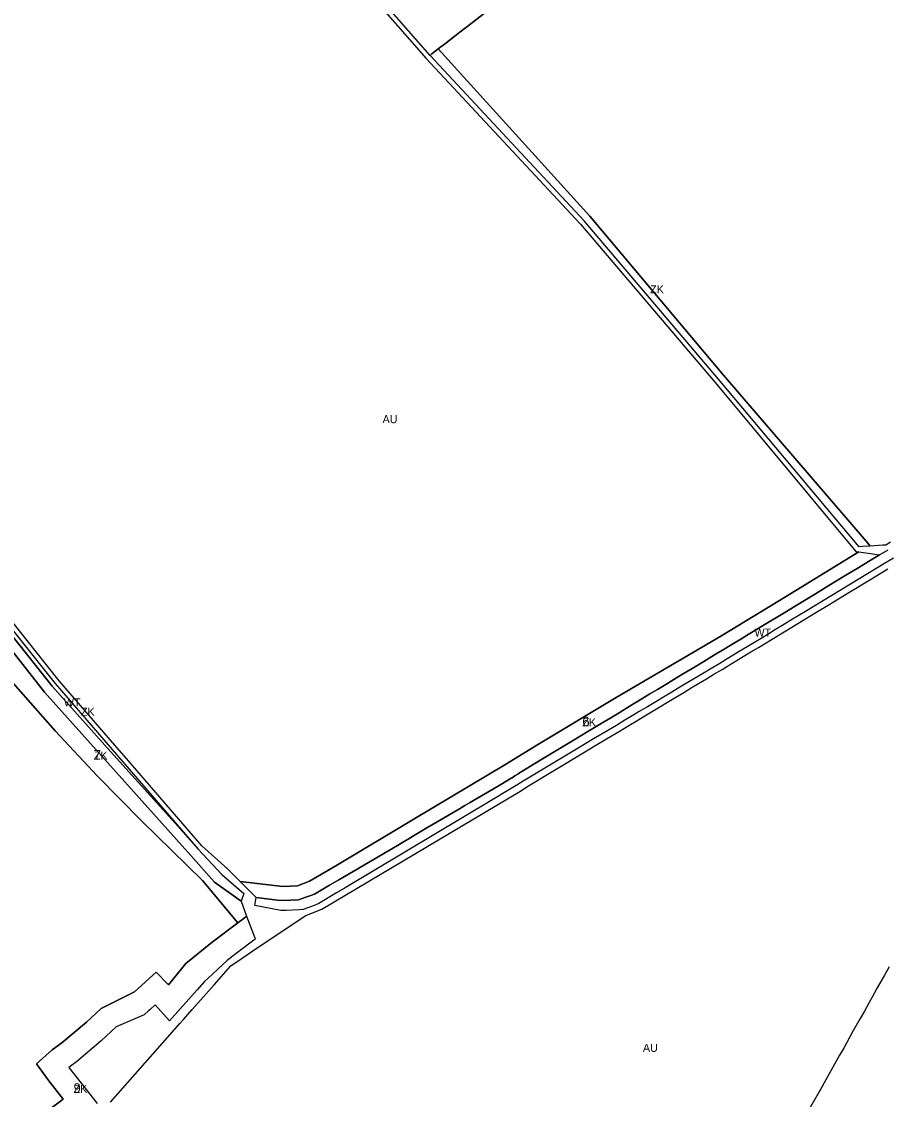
# Model space of a CAD drawing. Extents: x -537068 to -534056, y -1176840 to -1172401.
# Drawn here: x -536666 to -536126, y -1174218 to -1173545 of the extents above; entities that cross this region are included whole.
import ezdxf

# ---------------------------------------------------------------- set-up
doc = ezdxf.new("R2010")
doc.units = 0
for name, color, linetype in [('90640013', 7, 'Continuous'), ('90710013', 7, 'Continuous'), ('90710023', 7, 'Continuous'), ('90750013', 7, 'Continuous'), ('90770013', 7, 'Continuous'), ('ID_navrh', 7, 'Continuous')]:
    doc.layers.add(name, color=color, linetype=linetype)

msp = doc.modelspace()

# ---------------------------------------------------------------- linework, layer by layer
at = {"layer": '90640013'}
for points in [[(-536121.73, -1173879.82), (-536127.22, -1173883.05), (-536176.7, -1173913.11), (-536185.79, -1173918.63), (-536189.8, -1173921.07), (-536195.38, -1173924.46), (-536199.57, -1173927.01), (-536204.4, -1173929.95), (-536208.57, -1173932.48), (-536213.16, -1173935.27), (-536218.04, -1173938.23), (-536222.45, -1173940.91), (-536226.54, -1173943.39), (-536227.42, -1173943.93), (-536231.29, -1173946.25), (-536236.3, -1173949.25), (-536241.08, -1173952.11), (-536246, -1173955.05), (-536250.59, -1173957.8), (-536255.11, -1173960.5), (-536260.16, -1173963.52), (-536265.33, -1173966.62), (-536270.12, -1173969.49), (-536275.36, -1173972.62), (-536280.48, -1173975.69), (-536284.89, -1173978.33), (-536289.57, -1173981.13), (-536294.82, -1173984.27), (-536299.82, -1173987.26), (-536309.03, -1173992.77), (-536318.71, -1173998.56), (-536337.32, -1174009.7), (-536351.98, -1174018.47), (-536352.31, -1174018.69), (-536354.72, -1174020.24), (-536357, -1174021.72), (-536357.31, -1174021.92), (-536363.65, -1174025.71), (-536371.59, -1174030.46), (-536464.2, -1174085.8), (-536469.57, -1174089.01), (-536480.57, -1174095.59), (-536484.71, -1174097.18), (-536490.52, -1174099.41), (-536492.89, -1174099.52), (-536500.99, -1174099.88), (-536504.45, -1174100.04), (-536520.56, -1174096.89), (-536519.81, -1174091.88), (-536506.47, -1174093.52), (-536504.12, -1174093.81), (-536498.18, -1174093.56), (-536493.33, -1174093.35), (-536488.7, -1174091.7), (-536486.93, -1174091.07), (-536483.39, -1174089.81), (-536477.07, -1174086.08), (-536473.9, -1174084.21), (-536473.56, -1174084.01), (-536468.2, -1174080.85), (-536459.25, -1174075.58), (-536449.69, -1174069.95), (-536431.62, -1174059.3), (-536413.11, -1174048.39), (-536402.81, -1174042.32), (-536392.81, -1174036.42), (-536389.47, -1174034.45), (-536386.11, -1174032.47), (-536382.96, -1174030.62), (-536378.98, -1174028.27), (-536375.12, -1174025.99), (-536367.07, -1174021.24), (-536360.44, -1174017.34), (-536360.3, -1174017.26), (-536359.97, -1174017.04), (-536358.13, -1174015.83), (-536356.37, -1174014.68), (-536355.33, -1174014.01), (-536355, -1174013.79), (-536340.85, -1174005.23), (-536322.18, -1173993.93), (-536312.57, -1173988.11), (-536303.28, -1173982.49), (-536298.34, -1173979.5), (-536293.15, -1173976.36), (-536288.49, -1173973.54), (-536284.02, -1173970.84), (-536278.95, -1173967.77), (-536273.84, -1173964.67), (-536269.08, -1173961.79), (-536263.89, -1173958.65), (-536258.88, -1173955.62), (-536254.51, -1173952.98), (-536249.9, -1173950.19), (-536245.06, -1173947.26), (-536240.18, -1173944.31), (-536235.25, -1173941.33), (-536230.77, -1173938.62), (-536230.5, -1173938.46), (-536226.43, -1173935.99), (-536221.98, -1173933.29), (-536217.1, -1173930.33), (-536212.56, -1173927.58), (-536208.34, -1173925.02), (-536203.54, -1173922.11), (-536199.34, -1173919.56), (-536193.84, -1173916.22), (-536189.66, -1173913.69), (-536180.47, -1173908.12), (-536170.43, -1173902.03), (-536162.02, -1173896.93), (-536152.44, -1173891.12), (-536143.43, -1173885.65), (-536134.51, -1173880.24), (-536130.48, -1173877.8), (-536124.97, -1173874.53)], [(-536699.42, -1173894.17), (-536647.23, -1173959.79), (-536610.71, -1174000.56), (-536570.46, -1174045.5), (-536556.08, -1174061.56), (-536541.22, -1174077.55), (-536527.55, -1174089.36), (-536529.27, -1174094.11), (-536545.85, -1174082.18), (-536560.66, -1174065.67), (-536651.93, -1173963.52), (-536704.04, -1173897.38)]]:
    msp.add_lwpolyline(points, dxfattribs=at)
at = {"layer": '90710013'}
for points in [[(-536136.18, -1173872.29), (-536141, -1173872.6), (-536143.05, -1173872.73), (-536230.91, -1173768.07), (-536314.98, -1173669.12), (-536411.22, -1173565.66), (-536410.01, -1173564.67), (-536406.18, -1173561.55), (-536311.35, -1173666.13), (-536227.92, -1173765.45), (-536138.84, -1173869.19)], [(-536700.88, -1173882.54), (-536699.15, -1173887.54), (-536697.36, -1173892.73), (-536679.38, -1173915.34), (-536653.7, -1173947.64), (-536645.27, -1173958.23), (-536607.01, -1174002.55), (-536556.08, -1174061.56), (-536570.46, -1174045.5), (-536610.71, -1174000.56), (-536647.23, -1173959.79), (-536699.42, -1173894.17), (-536701.41, -1173891.5), (-536702.47, -1173890.09), (-536700.72, -1173886.71), (-536700.84, -1173883.54)]]:
    msp.add_lwpolyline(points, close=True, dxfattribs=at)
at = {"layer": '90710023'}
for points in [[(-536143.4, -1173875.91), (-536137.45, -1173876.78), (-536130.48, -1173877.8), (-536134.51, -1173880.24), (-536143.43, -1173885.65), (-536152.44, -1173891.12), (-536162.02, -1173896.93), (-536170.43, -1173902.03), (-536180.47, -1173908.12), (-536189.66, -1173913.69), (-536193.84, -1173916.22), (-536199.34, -1173919.56), (-536203.54, -1173922.11), (-536208.34, -1173925.02), (-536212.56, -1173927.58), (-536217.1, -1173930.33), (-536221.98, -1173933.29), (-536226.43, -1173935.99), (-536230.5, -1173938.46), (-536230.77, -1173938.62), (-536235.25, -1173941.33), (-536240.18, -1173944.31), (-536245.06, -1173947.26), (-536249.9, -1173950.19), (-536254.51, -1173952.98), (-536258.88, -1173955.62), (-536263.89, -1173958.65), (-536269.08, -1173961.79), (-536273.84, -1173964.67), (-536278.95, -1173967.77), (-536284.02, -1173970.84), (-536288.49, -1173973.54), (-536293.15, -1173976.36), (-536298.34, -1173979.5), (-536303.28, -1173982.49), (-536312.57, -1173988.11), (-536322.18, -1173993.93), (-536340.85, -1174005.23), (-536355, -1174013.79), (-536355.33, -1174014.01), (-536356.37, -1174014.68), (-536358.13, -1174015.83), (-536359.97, -1174017.04), (-536360.3, -1174017.26), (-536360.44, -1174017.34), (-536367.07, -1174021.24), (-536375.12, -1174025.99), (-536378.98, -1174028.27), (-536382.96, -1174030.62), (-536386.11, -1174032.47), (-536389.47, -1174034.45), (-536392.81, -1174036.42), (-536402.81, -1174042.32), (-536413.11, -1174048.39), (-536431.62, -1174059.3), (-536449.69, -1174069.95), (-536459.25, -1174075.58), (-536468.2, -1174080.85), (-536473.56, -1174084.01), (-536473.9, -1174084.21), (-536477.07, -1174086.08), (-536483.39, -1174089.81), (-536486.93, -1174091.07), (-536488.7, -1174091.7), (-536493.33, -1174093.35), (-536498.18, -1174093.56), (-536504.12, -1174093.81), (-536506.47, -1174093.52), (-536519.81, -1174091.88), (-536529.84, -1174081.82), (-536503.22, -1174084.89), (-536494, -1174084.47), (-536486.42, -1174081.59), (-536470.01, -1174071.96), (-536420.7, -1174042.51), (-536364.52, -1174008.91), (-536343.36, -1173995.97), (-536295.01, -1173966.93), (-536229.61, -1173928.51), (-536189.18, -1173903.97)], [(-536531.3, -1174107.64), (-536553.25, -1174081.23), (-536591.39, -1174043.89), (-536618.92, -1174015.95), (-536645.34, -1173987.75), (-536676.1, -1173952.69), (-536703.54, -1173915.67), (-536716.72, -1173897.04), (-536707.68, -1173892.89), (-536704.04, -1173897.38), (-536651.93, -1173963.52), (-536560.66, -1174065.67), (-536545.85, -1174082.18), (-536529.27, -1174094.11), (-536525.77, -1174103.45), (-536527.4, -1174104.68)]]:
    msp.add_lwpolyline(points, close=True, dxfattribs=at)
msp.add_lwpolyline([(-536655.27, -1174229.14), (-536640.42, -1174217.81), (-536649.38, -1174206.4), (-536656.94, -1174195.79), (-536647.14, -1174187.01), (-536641.13, -1174182.57), (-536625.9, -1174169.67), (-536616.62, -1174161.14), (-536595.84, -1174150.89), (-536582.3, -1174138.54), (-536574.58, -1174146.41), (-536563.66, -1174133), (-536547.35, -1174119.82), (-536531.3, -1174107.64), (-536527.4, -1174104.68), (-536525.77, -1174103.45), (-536520.69, -1174116.97), (-536520.35, -1174117.88), (-536532.23, -1174126.8), (-536537.99, -1174131.12), (-536549.77, -1174142.2), (-536552.09, -1174144.39), (-536556.68, -1174149.57), (-536573.89, -1174168.98), (-536582.98, -1174159), (-536585.99, -1174161.74), (-536586.97, -1174162.65), (-536589.69, -1174165.16), (-536607.24, -1174172.71), (-536616.56, -1174181.4), (-536632.01, -1174194.48), (-536636.91, -1174197.98), (-536629.05, -1174207.9), (-536619.11, -1174220.46)], dxfattribs=at)
at = {"layer": '90750013'}
for points in [[(-536453.82, -1173521.55), (-536413.54, -1173567.56), (-536317.29, -1173671.03), (-536233.17, -1173770.05), (-536145.26, -1173875.64), (-536143.4, -1173875.91), (-536189.18, -1173903.97), (-536229.61, -1173928.51), (-536295.01, -1173966.93), (-536343.36, -1173995.97), (-536364.52, -1174008.91), (-536420.7, -1174042.51), (-536470.01, -1174071.96), (-536486.42, -1174081.59), (-536494, -1174084.47), (-536503.22, -1174084.89), (-536529.84, -1174081.82), (-536537.66, -1174073.99), (-536553.84, -1174059.56), (-536599.64, -1174006.51), (-536608.14, -1173996.67), (-536642.93, -1173956.37), (-536694.89, -1173891.01)], [(-536123.52, -1173869.83), (-536126.5, -1173871.67), (-536128.27, -1173871.78), (-536136.18, -1173872.29), (-536138.84, -1173869.19), (-536227.92, -1173765.45), (-536311.35, -1173666.13), (-536406.18, -1173561.55), (-536401.43, -1173557.92), (-536392.57, -1173551.14), (-536384.64, -1173545.08), (-536376.87, -1173539.13)], [(-536610.87, -1174219.78), (-536567.42, -1174170.5), (-536565.29, -1174168.08), (-536559.76, -1174161.82), (-536552.98, -1174154.14), (-536546.13, -1174146.38), (-536535.64, -1174134.48), (-536529.18, -1174130.14), (-536518.53, -1174122.98), (-536488.85, -1174103.03), (-536478.83, -1174099.14), (-536355.06, -1174025.61), (-536349.67, -1174022.12), (-536316.18, -1174001.94), (-536306.49, -1173996.1), (-536297.39, -1173990.62), (-536292.37, -1173987.6), (-536287.1, -1173984.43), (-536282.42, -1173981.61), (-536278.07, -1173978.99), (-536272.94, -1173975.9), (-536267.64, -1173972.7), (-536262.85, -1173969.81), (-536257.71, -1173966.72), (-536252.66, -1173963.68), (-536248.06, -1173960.91), (-536243.5, -1173958.16), (-536238.56, -1173955.18), (-536233.87, -1173952.35), (-536228.82, -1173949.31), (-536225.35, -1173947.22), (-536224.08, -1173946.45), (-536219.98, -1173943.96), (-536215.59, -1173941.3), (-536210.71, -1173938.34), (-536206.08, -1173935.54), (-536169.22, -1173913.18), (-536162.57, -1173909.15), (-536149.6, -1173901.28), (-536135.42, -1173892.68), (-536125.26, -1173886.52)], [(-536676.1, -1173952.69), (-536645.34, -1173987.75), (-536618.92, -1174015.95), (-536591.39, -1174043.89), (-536553.25, -1174081.23), (-536531.3, -1174107.64), (-536547.35, -1174119.82), (-536563.66, -1174133), (-536574.58, -1174146.41), (-536582.3, -1174138.54), (-536595.84, -1174150.89), (-536616.62, -1174161.14), (-536625.9, -1174169.67), (-536641.13, -1174182.57), (-536647.14, -1174187.01), (-536656.94, -1174195.79), (-536649.38, -1174206.4), (-536640.42, -1174217.81), (-536655.27, -1174229.14)], [(-536124.46, -1174135.08), (-536127.34, -1174140.28), (-536131.8, -1174148.29), (-536133.51, -1174151.34), (-536134.98, -1174154.09), (-536136.81, -1174157.4), (-536139.87, -1174162.9), (-536142.44, -1174167.42), (-536147.2, -1174175.86), (-536152.46, -1174185.52), (-536155.4, -1174190.41), (-536164.05, -1174205.81), (-536167.39, -1174211.76), (-536185.2, -1174242.92)]]:
    msp.add_lwpolyline(points, dxfattribs=at)
at = {"layer": '90770013'}
msp.add_lwpolyline([(-536531.67, -1173437.87), (-536528.92, -1173435.58), (-536525.93, -1173433.09), (-536511.38, -1173420.98), (-536508.14, -1173419.59), (-536499.62, -1173415.94), (-536489.19, -1173411.48), (-536471.93, -1173404.1), (-536453.14, -1173425.5), (-536419.21, -1173464.14), (-536364.3, -1173526.67), (-536376.51, -1173538.77), (-536376.87, -1173539.13), (-536384.64, -1173545.08), (-536392.57, -1173551.14), (-536401.43, -1173557.92), (-536406.18, -1173561.55), (-536410.01, -1173564.67), (-536411.22, -1173565.66), (-536451.77, -1173519.35), (-536493.93, -1173475.47), (-536528.81, -1173440.72)], close=True, dxfattribs=at)

# ---------------------------------------------------------------- texts
at = {"layer": '90640013'}
for rotation, p in [(0, (-536208.51, -1173928.78)), (360, (-536639.94, -1173972.43))]:
    msp.add_text('WT', height=5, rotation=rotation, dxfattribs=at).set_placement(p)
at = {"layer": '90710013'}
for p in [(-536273.7, -1173714.33), (-536629.28, -1173978.3)]:
    msp.add_text('ZK', height=5, rotation=0, dxfattribs=at).set_placement(p)
at = {"layer": '90710023'}
for p in [(-536316.03, -1173984.86), (-536621.24, -1174005.67), (-536633.89, -1174213.91)]:
    msp.add_text('ZK', height=5, rotation=0, dxfattribs=at).set_placement(p)
at = {"layer": '90750013'}
for rotation, p in [(0, (-536440.85, -1173795.45)), (360, (-536278.22, -1174188.32))]:
    msp.add_text('AU', height=5, rotation=rotation, dxfattribs=at).set_placement(p)
at = {"layer": 'ID_navrh'}
for s, rotation, p in [('6', 0, (-536316.03, -1173984.86)), ('7', 360, (-536621.24, -1174005.67)), ('9', 0, (-536633.89, -1174213.91))]:
    msp.add_text(s, height=6, rotation=rotation, dxfattribs=at).set_placement(p)

doc.saveas('drawing.dxf')
